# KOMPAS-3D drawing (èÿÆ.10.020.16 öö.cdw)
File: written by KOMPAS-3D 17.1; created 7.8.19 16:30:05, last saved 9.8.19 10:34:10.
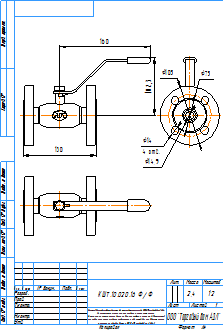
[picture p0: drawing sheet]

Sheet 1: A4, portrait

Title block, sheet 1: name: КШТ.10.020.16 Ф/Ф; material: Сталь 20  ГОСТ 1050-2013; mass: 2,4; sheets: 1; sheet format: A4; stored path: C:\Users\kka\KOMPAS_Work\Модели кранов для исследований\DN65\КШТ.10.065.16 СС.cdw

Views: Вид 1, Проекционный вид 2, Проекционный вид 3
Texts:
  kka
  adl
  Рама для чертежей
  Лит-Масса-Масштаб
  Материал-Предприятие
  Масштаб
  Изм.
  Лист
  № докум.
  Подп.
  Дата
  Лит.
  Разраб.
  Пров.
  Т.контр.
  Листов
  Внимание! Данный продукт является объектом авторского права ООО «Торговый Дом АДЛ».
  Запрещается изменение, копирование, распространение
  (в том числе путем копирования на другие сайты и ресурсы в Интернете)
  или любое иное использование информации и объектов без предварительного
  согласия правообладателя (ООО «Торговый Дом АДЛ»).
  Н.контр.
  Утв.
  ООО "Торговый дом АДЛ"
  Изменение
  Номер документа
  Подпись
  Обозначение документа
  Наименование изделия
  Масса изделия по ГОСТ 2.109-73
  Порядковый номер листа
  Общее количество листов в документе
  Характер работы, выполненной лицом, подписавшим документ
  Наименование или индекс предприятия, выпускающего документ
  Инв. № подл.
  Подп. и дата
  Взам. инв. №
  Инв. № дубл.
  Инвентарный номер подлинника по ГОСТ 2.501-68
  Подпись принявшего подлинник в отдел технической документации
  Инвентарный номер подлинника, взамен которого выпущен данный подлинник
  Инвентарный номер дубликата по ГОСТ 2.502-68
  Подпись принявшего дубликат в отдел технической документации
  Справ. №
  Перв. примен.
  Обозначение документа, взамен или на основании которого выпущен данный документ
  Обозначение документа, в котором впервые записан данный документ
  Подпись лица, копировавшего чертеж
  Обозначение формата листа
  !Рама для чертежа
Dimensions and other numbers on the sheet: 160; 102,3; 130; 14,9; 105; 75; 14; 4 отв.; 1:2; 1; 2,4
